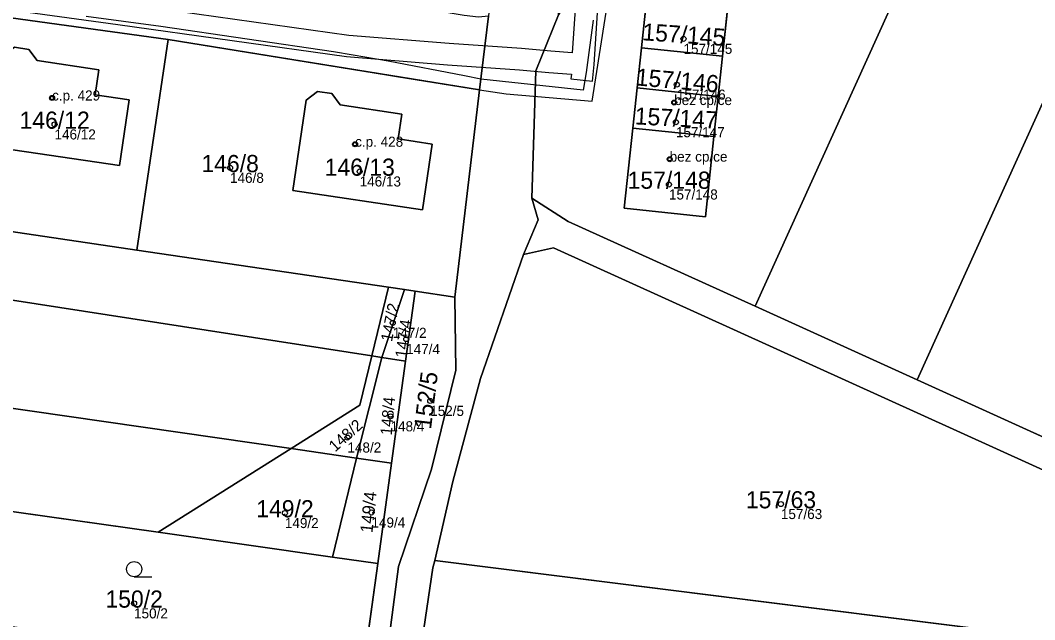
# Model space of a CAD drawing. Extents: x -603967 to -594699, y -1179315 to -1165625.
# Drawn here: x -598296.5 to -598196, y -1172641.9 to -1172582.6 of the extents above; entities that cross this region are included whole.
import ezdxf

# ---------------------------------------------------------------- set-up
doc = ezdxf.new("R2010")
doc.units = 0
for name, color, linetype in [('Definiční body', 7, 'Continuous'), ('Hranice parcel', 7, 'Continuous'), ('Parcelní čísla', 7, 'Continuous'), ('Polygon budovy', 7, 'Continuous'), ('Polygon parcely', 7, 'Continuous'), ('Věcná břemena k části', 7, 'Continuous'), ('Značky budov', 7, 'Continuous'), ('Značky kultur', 7, 'Continuous')]:
    doc.layers.add(name, color=color, linetype=linetype)

msp = doc.modelspace()

# ---------------------------------------------------------------- linework, layer by layer
at = {"layer": 'Definiční body'}
for centre in [(-598230.8, -1172584.39994), (-598231.46, -1172588.93994), (-598293.35, -1172590.25994), (-598231.72, -1172590.70994), (-598293.11, -1172592.87994), (-598231.55, -1172592.65994), (-598263.33, -1172594.83994), (-598232.17, -1172596.31994), (-598275.72, -1172597.17994), (-598262.88, -1172597.53994), (-598232.24, -1172598.82994), (-598259.6, -1172612.53994), (-598258.27, -1172614.14994), (-598255.89, -1172620.26994), (-598259.82, -1172621.79994), (-598264.09, -1172623.89994), (-598221.15, -1172630.48994), (-598270.29, -1172631.37994), (-598261.71, -1172631.32994), (-598285.23, -1172640.32994)]:
    msp.add_circle(centre, 0.25, dxfattribs=at)
at = {"layer": 'Hranice parcel'}
for p, q in [((-598223.71, -1172610.9), (-598181.54, -1172517.82)), ((-598207.65, -1172618.18), (-598165.48, -1172525.1)), ((-598313.07, -1172580.13), (-598281.85, -1172584.47)), ((-598234.96, -1172585.29), (-598234.32, -1172579.33)), ((-598226.31, -1172580.16), (-598226.94, -1172586.12)), ((-598250.13, -1172582.16), (-598251, -1172589.44)), ((-598281.85, -1172584.47), (-598284.96, -1172605.33)), ((-598251, -1172589.44), (-598281.85, -1172584.47)), ((-598235.39, -1172589.26), (-598234.96, -1172585.29)), ((-598234.96, -1172585.29), (-598226.94, -1172586.12)), ((-598226.94, -1172586.12), (-598227.37, -1172590.1)), ((-598235.81, -1172593.24), (-598235.39, -1172589.26)), ((-598235.39, -1172589.26), (-598227.37, -1172590.1)), ((-598251, -1172589.44), (-598253.44, -1172609.98)), ((-598227.37, -1172590.1), (-598227.79, -1172594.08)), ((-598235.81, -1172593.24), (-598227.79, -1172594.08)), ((-598284.96, -1172605.33), (-598316.14, -1172600.72)), ((-598349.31, -1172602.22), (-598261.68, -1172615.82)), ((-598260.02, -1172609.01), (-598284.96, -1172605.33)), ((-598261.68, -1172615.82), (-598260.02, -1172609.01)), ((-598260.69, -1172615.97), (-598258.44, -1172609.24)), ((-598258.44, -1172609.24), (-598260.02, -1172609.01)), ((-598258.44, -1172609.24), (-598257.38, -1172609.4)), ((-598257.38, -1172609.4), (-598258.33, -1172616.34)), ((-598253.44, -1172609.98), (-598257.38, -1172609.4)), ((-598223.71, -1172610.9), (-598207.65, -1172618.18)), ((-598350.81, -1172613.29), (-598269.67, -1172624.98)), ((-598263.2, -1172625.94), (-598260.69, -1172615.97)), ((-598261.68, -1172615.82), (-598260.69, -1172615.97)), ((-598258.33, -1172616.34), (-598260.69, -1172615.97)), ((-598258.33, -1172616.34), (-598259.72, -1172626.45)), ((-598207.65, -1172618.18), (-598191.44, -1172625.54)), ((-598282.83, -1172633.27), (-598269.67, -1172624.98)), ((-598269.67, -1172624.98), (-598263.2, -1172625.94)), ((-598265.56, -1172635.74), (-598263.2, -1172625.94)), ((-598263.2, -1172625.94), (-598259.72, -1172626.45)), ((-598259.72, -1172626.45), (-598261.08, -1172636.38)), ((-598308.36, -1172629.68), (-598282.83, -1172633.27)), ((-598282.83, -1172633.27), (-598265.56, -1172635.74)), ((-598261.08, -1172636.38), (-598265.56, -1172635.74)), ((-598262.64, -1172647.62), (-598261.08, -1172636.38)), ((-598255.45, -1172636.08), (-598178.95, -1172645.7))]:
    msp.add_line(p, q, dxfattribs=at)
for points in [[(-598245.82, -1172600.17), (-598245.42, -1172587.58), (-598243.18, -1172582.01)], [(-598294.84, -1172586.56), (-598288.72, -1172587.46), (-598289.08, -1172589.94), (-598285.71, -1172590.44), (-598286.66, -1172596.95), (-598299.51, -1172595.06), (-598298.19, -1172586.07), (-598297.06, -1172585.23), (-598295.66, -1172585.44), (-598294.84, -1172586.56)], [(-598255.71, -1172594.82), (-598256.67, -1172601.33), (-598269.51, -1172599.44), (-598268.19, -1172590.46), (-598267.05, -1172589.61), (-598265.65, -1172589.82), (-598264.81, -1172590.94), (-598258.71, -1172591.85), (-598259.07, -1172594.32), (-598255.71, -1172594.82)], [(-598227.79, -1172594.08), (-598228.63, -1172602.03), (-598236.67, -1172601.19), (-598235.81, -1172593.24)], [(-598246.66, -1172605.78), (-598245.19, -1172602.33), (-598245.82, -1172600.17)], [(-598245.82, -1172600.17), (-598242.24, -1172602.51), (-598223.71, -1172610.9)], [(-598178.02, -1172634.9), (-598243.69, -1172605.12), (-598246.66, -1172605.78)], [(-598255.45, -1172636.08), (-598253.64, -1172628.24), (-598250.92, -1172618.05), (-598246.66, -1172605.78)], [(-598265.92, -1172686), (-598265.51, -1172686.06), (-598259.05, -1172636.67), (-598255.76, -1172627.04), (-598253.35, -1172617.23), (-598253.44, -1172609.98)], [(-598269.67, -1172624.98), (-598262.86, -1172620.69), (-598261.68, -1172615.82)], [(-598261.46, -1172676.21), (-598255.62, -1172636.81), (-598255.45, -1172636.08)]]:
    msp.add_lwpolyline(points, dxfattribs=at)
at = {"layer": 'Polygon budovy'}
for points in [[(-598288.72, -1172587.46), (-598294.84, -1172586.56), (-598295.66, -1172585.44), (-598297.06, -1172585.23), (-598298.19, -1172586.07), (-598299.51, -1172595.06), (-598286.66, -1172596.95), (-598285.71, -1172590.44), (-598289.08, -1172589.94)], [(-598235.81, -1172593.24), (-598227.79, -1172594.08), (-598227.37, -1172590.1), (-598235.39, -1172589.26)], [(-598269.51, -1172599.44), (-598256.67, -1172601.33), (-598255.71, -1172594.82), (-598259.07, -1172594.32), (-598258.71, -1172591.85), (-598264.81, -1172590.94), (-598265.65, -1172589.82), (-598267.05, -1172589.61), (-598268.19, -1172590.46)], [(-598236.67, -1172601.19), (-598228.63, -1172602.03), (-598227.79, -1172594.08), (-598235.81, -1172593.24)]]:
    msp.add_lwpolyline(points, close=True, dxfattribs=at)
at = {"layer": 'Polygon parcely'}
for points in [[(-598261.46, -1172676.21), (-598255.62, -1172636.81), (-598255.45, -1172636.08), (-598253.64, -1172628.24), (-598250.92, -1172618.05), (-598246.66, -1172605.78), (-598245.19, -1172602.33), (-598245.82, -1172600.17), (-598245.42, -1172587.58), (-598243.18, -1172582.01), (-598243.32, -1172534.93), (-598242.5, -1172518.68), (-598240.72, -1172512.95), (-598236.93, -1172506.23), (-598161.24, -1172422.87)], [(-598219.43, -1172472.18), (-598224.34, -1172477.3), (-598227.61, -1172480.61), (-598231.12, -1172484.14), (-598236.49, -1172489.55), (-598243.84, -1172496.8), (-598250.01, -1172507.18), (-598254.03, -1172515.65), (-598254.06, -1172520.59), (-598252.37, -1172523.35), (-598251.53, -1172528.85), (-598250.75, -1172532.5), (-598249.37, -1172551.13), (-598249.27, -1172552.06), (-598250.05, -1172581.46), (-598250.13, -1172582.16), (-598251, -1172589.44), (-598253.44, -1172609.98), (-598253.35, -1172617.23), (-598255.76, -1172627.04), (-598259.05, -1172636.67), (-598265.51, -1172686.06)], [(-598313.07, -1172580.13), (-598281.85, -1172584.47), (-598251, -1172589.44), (-598250.13, -1172582.16), (-598251.12, -1172582.24), (-598252.52, -1172582.1), (-598261.54, -1172580.52), (-598268.46, -1172579.38), (-598274.4, -1172578.51), (-598362.94, -1172566.18)], [(-598147.31, -1172645.53), (-598156.91, -1172641.18), (-598162.02, -1172638.87), (-598176.73, -1172632.2), (-598191.44, -1172625.54), (-598207.65, -1172618.18), (-598223.71, -1172610.9), (-598242.24, -1172602.51), (-598245.82, -1172600.17), (-598245.19, -1172602.33), (-598246.66, -1172605.78), (-598243.69, -1172605.12), (-598178.02, -1172634.9), (-598175.13, -1172636.24), (-598090.13, -1172674.74)]]:
    msp.add_lwpolyline(points, dxfattribs=at)
for points in [[(-598165.48, -1172525.1), (-598207.65, -1172618.18), (-598191.44, -1172625.54), (-598107.31, -1172439.82), (-598123.41, -1172432.22), (-598124.65, -1172434.95)], [(-598197.25, -1172505.23), (-598221.79, -1172545.44), (-598226.22, -1172553.01), (-598226.2, -1172554.22), (-598226.08, -1172562.22), (-598226.02, -1172566.22), (-598225.96, -1172570.22), (-598225.9, -1172574.22), (-598233.9, -1172574.34), (-598233.96, -1172570.34), (-598234.02, -1172566.34), (-598243.18, -1172582.01), (-598245.42, -1172587.58), (-598245.82, -1172600.17), (-598242.24, -1172602.51), (-598223.71, -1172610.9), (-598181.54, -1172517.82), (-598179.48, -1172513.27)], [(-598207.65, -1172618.18), (-598165.48, -1172525.1), (-598181.54, -1172517.82), (-598223.71, -1172610.9)], [(-598235.81, -1172593.24), (-598235.39, -1172589.26), (-598234.96, -1172585.29), (-598234.32, -1172579.33), (-598233.89, -1172575.35), (-598225.89, -1172576.18), (-598226.31, -1172580.16), (-598226.94, -1172586.12), (-598227.37, -1172590.1), (-598227.79, -1172594.08), (-598228.63, -1172602.03), (-598236.67, -1172601.19)], [(-598316.14, -1172600.72), (-598284.96, -1172605.33), (-598281.85, -1172584.47), (-598313.07, -1172580.13)], [(-598226.94, -1172586.12), (-598226.31, -1172580.16), (-598234.32, -1172579.33), (-598234.96, -1172585.29)], [(-598294.84, -1172586.56), (-598295.66, -1172585.44), (-598297.06, -1172585.23), (-598298.19, -1172586.07), (-598299.51, -1172595.06), (-598286.66, -1172596.95), (-598285.71, -1172590.44), (-598289.08, -1172589.94), (-598288.72, -1172587.46)], [(-598294.84, -1172586.56), (-598288.72, -1172587.46), (-598289.08, -1172589.94), (-598285.71, -1172590.44), (-598286.66, -1172596.95), (-598299.51, -1172595.06), (-598298.19, -1172586.07), (-598297.06, -1172585.23), (-598295.66, -1172585.44)], [(-598257.38, -1172609.4), (-598253.44, -1172609.98), (-598251, -1172589.44), (-598281.85, -1172584.47), (-598284.96, -1172605.33), (-598260.02, -1172609.01), (-598258.44, -1172609.24)], [(-598227.37, -1172590.1), (-598226.94, -1172586.12), (-598234.96, -1172585.29), (-598235.39, -1172589.26)], [(-598227.79, -1172594.08), (-598227.37, -1172590.1), (-598235.39, -1172589.26), (-598235.81, -1172593.24)], [(-598255.71, -1172594.82), (-598256.67, -1172601.33), (-598269.51, -1172599.44), (-598268.19, -1172590.46), (-598267.05, -1172589.61), (-598265.65, -1172589.82), (-598264.81, -1172590.94), (-598258.71, -1172591.85), (-598259.07, -1172594.32)], [(-598255.71, -1172594.82), (-598259.07, -1172594.32), (-598258.71, -1172591.85), (-598264.81, -1172590.94), (-598265.65, -1172589.82), (-598267.05, -1172589.61), (-598268.19, -1172590.46), (-598269.51, -1172599.44), (-598256.67, -1172601.33)], [(-598227.79, -1172594.08), (-598235.81, -1172593.24), (-598236.67, -1172601.19), (-598228.63, -1172602.03)], [(-598348.5, -1172596.1), (-598349.31, -1172602.22), (-598261.68, -1172615.82), (-598260.02, -1172609.01), (-598284.96, -1172605.33), (-598316.14, -1172600.72)], [(-598349.31, -1172602.22), (-598350.81, -1172613.29), (-598269.67, -1172624.98), (-598262.86, -1172620.69), (-598261.68, -1172615.82)], [(-598178.02, -1172634.9), (-598243.69, -1172605.12), (-598246.66, -1172605.78), (-598250.92, -1172618.05), (-598253.64, -1172628.24), (-598255.45, -1172636.08), (-598178.95, -1172645.7)], [(-598264.32, -1172659.14), (-598268.96, -1172658.48), (-598270.9, -1172671.66), (-598272.85, -1172684.97), (-598265.92, -1172686), (-598265.51, -1172686.06), (-598259.05, -1172636.67), (-598255.76, -1172627.04), (-598253.35, -1172617.23), (-598253.44, -1172609.98), (-598257.38, -1172609.4), (-598258.33, -1172616.34), (-598259.72, -1172626.45), (-598261.08, -1172636.38), (-598262.64, -1172647.62)], [(-598258.44, -1172609.24), (-598260.02, -1172609.01), (-598261.68, -1172615.82), (-598260.69, -1172615.97)], [(-598258.44, -1172609.24), (-598260.69, -1172615.97), (-598258.33, -1172616.34), (-598257.38, -1172609.4)], [(-598350.81, -1172613.29), (-598352.21, -1172623.52), (-598308.36, -1172629.68), (-598282.83, -1172633.27), (-598269.67, -1172624.98)], [(-598263.2, -1172625.94), (-598260.69, -1172615.97), (-598261.68, -1172615.82), (-598262.86, -1172620.69), (-598269.67, -1172624.98)], [(-598260.69, -1172615.97), (-598263.2, -1172625.94), (-598259.72, -1172626.45), (-598258.33, -1172616.34)], [(-598263.2, -1172625.94), (-598269.67, -1172624.98), (-598282.83, -1172633.27), (-598265.56, -1172635.74)], [(-598263.2, -1172625.94), (-598265.56, -1172635.74), (-598261.08, -1172636.38), (-598259.72, -1172626.45)], [(-598267.22, -1172646.96), (-598262.64, -1172647.62), (-598261.08, -1172636.38), (-598265.56, -1172635.74), (-598282.83, -1172633.27), (-598308.36, -1172629.68), (-598309.94, -1172640.89), (-598298.94, -1172642.4)], [(-598178.95, -1172645.7), (-598255.45, -1172636.08), (-598255.62, -1172636.81), (-598261.46, -1172676.21), (-598182.43, -1172686.14)]]:
    msp.add_lwpolyline(points, close=True, dxfattribs=at)
at = {"layer": 'Věcná břemena k části'}
for points in [[(-598313.07, -1172580.13), (-598290.2, -1172583.31), (-598289.19, -1172583.45), (-598281.85, -1172584.47), (-598260.22, -1172587.95), (-598259.22, -1172588.12), (-598251, -1172589.44), (-598248.36, -1172589.84), (-598239.86, -1172590.57), (-598238.2, -1172580.03), (-598237.51, -1172564.09), (-598237.94, -1172547.32), (-598238.67, -1172539.73), (-598234.23, -1172540), (-598230.8, -1172536.02), (-598229.03, -1172526.25), (-598229.61, -1172519.66), (-598236.79, -1172518.31), (-598238.67, -1172518.55), (-598239.41, -1172517.85), (-598243.94, -1172515.95), (-598280.34, -1172499.78)], [(-598313.13, -1172579.33), (-598286.85, -1172582.97), (-598264.2, -1172586.15), (-598254.17, -1172586.96), (-598247.04, -1172587.46), (-598244.13, -1172587.73), (-598241.91, -1172587.89), (-598241.96, -1172588.36), (-598239.82, -1172588.58), (-598239.64, -1172586.94), (-598238.53, -1172569.51)], [(-598240.69, -1172569.45), (-598241.82, -1172585.79), (-598243.95, -1172585.63), (-598246.86, -1172585.36), (-598254.01, -1172584.86), (-598263.96, -1172584.07), (-598286.55, -1172580.89)], [(-598239.74, -1172582.56), (-598240.43, -1172587.73), (-598240.73, -1172589.47), (-598250.88, -1172588.4), (-598252.49, -1172588.06), (-598260.07, -1172586.62), (-598263.51, -1172586.02), (-598265.47, -1172585.7), (-598282.57, -1172583.19), (-598289.97, -1172582.17)]]:
    msp.add_lwpolyline(points, dxfattribs=at)
at = {"layer": 'Značky budov'}
for centre in [(-598293.3568, -1172590.25916), (-598231.7268, -1172590.70916), (-598263.3368, -1172594.83916), (-598232.1768, -1172596.31916)]:
    msp.add_circle(centre, 0.175, dxfattribs=at)
at = {"layer": 'Značky kultur'}
msp.add_line((-598285.223, -1172637.69), (-598283.473, -1172637.69), dxfattribs=at)
msp.add_circle((-598285.22286, -1172636.93981), 0.75, dxfattribs=at)

# ---------------------------------------------------------------- texts
at = {"layer": 'Definiční body'}
for s, p in [('157/145', (-598230.8, -1172585.889)), ('c.p. 429', (-598293.35, -1172590.51)), ('bez cp/ce', (-598231.72, -1172590.96)), ('157/146', (-598231.46, -1172590.429)), ('146/12', (-598293.11, -1172594.369)), ('157/147', (-598231.55, -1172594.149)), ('c.p. 428', (-598263.33, -1172595.09)), ('bez cp/ce', (-598232.17, -1172596.57)), ('146/8', (-598275.72, -1172598.669)), ('146/13', (-598262.88, -1172599.029)), ('157/148', (-598232.24, -1172600.319)), ('147/2', (-598259.6, -1172614.029)), ('147/4', (-598258.27, -1172615.639)), ('152/5', (-598255.89, -1172621.759)), ('148/4', (-598259.82, -1172623.289)), ('148/2', (-598264.09, -1172625.389)), ('157/63', (-598221.15, -1172631.979)), ('149/2', (-598270.29, -1172632.869)), ('149/4', (-598261.71, -1172632.819)), ('150/2', (-598285.23, -1172641.819))]:
    msp.add_text(s, height=0.999996, dxfattribs=at).set_placement(p)
at = {"layer": 'Parcelní čísla'}
for s, height, rotation, p in [('157/145', 1.699998, 356, (-598234.916, -1172584.538)), ('157/146', 1.699998, 355, (-598235.578, -1172589.006)), ('157/147', 1.699998, 357, (-598235.663, -1172592.87)), ('147/2', 1.138998, 79, (-598259.683, -1172614.459)), ('147/4', 1.138998, 82, (-598258.252, -1172616.071)), ('152/5', 1.699998, 83, (-598255.813, -1172623.136)), ('148/4', 1.138998, 85, (-598259.701, -1172623.717)), ('148/2', 1.138998, 42, (-598265.311, -1172625.383)), ('149/4', 1.224, 84, (-598261.619, -1172633.392))]:
    msp.add_text(s, height=height, rotation=rotation, dxfattribs=at).set_placement(p)
for s, p in [('146/12', (-598296.576, -1172593.305)), ('146/8', (-598278.556, -1172597.605)), ('146/13', (-598266.346, -1172597.965)), ('157/148', (-598236.336, -1172599.255)), ('157/63', (-598224.616, -1172630.915)), ('149/2', (-598273.126, -1172631.805)), ('150/2', (-598288.066, -1172640.755))]:
    msp.add_text(s, height=1.699998, dxfattribs=at).set_placement(p)

doc.saveas('drawing.dxf')
